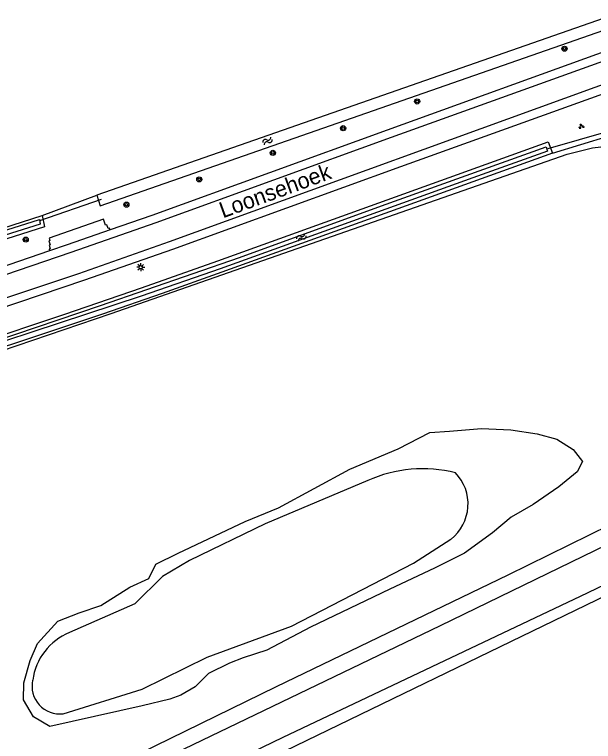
# Model space of a CAD drawing. Extents: x 134297 to 137000, y 403500 to 406000.
# Drawn here: x 136102.7 to 136193, y 404433.4 to 404546.7 of the extents above; entities that cross this region are included whole.
import ezdxf

# ---------------------------------------------------------------- set-up
doc = ezdxf.new("R2010")
doc.units = 0
for name, color, linetype in [('gg-afsc-draadraster', 7, 'Continuous'), ('gg-afsc-lijn draadraster', 7, 'Continuous'), ('gg-anno-openbare ruimte label', 7, 'Continuous'), ('gg-knt-verharding', 7, 'Continuous'), ('gg-knt-verharding nz', 7, 'Continuous'), ('gg-kntw-bovenkant insteek waterloop', 7, 'Continuous'), ('gg-kntw-waterlijn', 7, 'Continuous'), ('gg-kwrk-duiker nz buis', 7, 'Continuous'), ('gt-grn-groengrens', 7, 'Continuous'), ('gt-symb-boom', 7, 'Continuous'), ('gt-symb-groenvak', 7, 'Continuous'), ('gt-symb-lichtmast', 7, 'Continuous'), ('gt-symb-watersymbool', 7, 'Continuous')]:
    doc.layers.add(name, color=color, linetype=linetype)

# ---------------------------------------------------------------- blocks, each defined once
blk = doc.blocks.new('gt0-BOOM')
at = {"layer": 'gt-symb-boom'}
for radius in [0.4, 0.2]:
    blk.add_circle((0, 0), radius, dxfattribs=at)
blk = doc.blocks.new('gt0-GRVAK')
at = {"layer": 'gt-symb-groenvak'}
for p, q in [((-0.11, 0.19), (-0.23, 0.24)), ((-0.18, 0.15), (0.09, 0.15)), ((-0.09, 0.21), (-0.16, 0.32)), ((-0.05, 0.21), (-0.05, 0.39)), ((0, 0.21), (0.06, 0.32)), ((0.01, 0.19), (0.13, 0.24)), ((0.26, -0.05), (0.2, 0.06)), ((0.3, -0.05), (0.3, 0.13)), ((0.35, -0.05), (0.41, 0.06)), ((-0.24, -0.23), (-0.36, -0.18)), ((-0.32, -0.26), (-0.05, -0.26)), ((-0.23, -0.21), (-0.29, -0.09)), ((-0.18, -0.2), (-0.18, -0.02)), ((-0.14, -0.21), (-0.07, -0.09)), ((-0.12, -0.23), (0, -0.18)), ((0.24, -0.07), (0.12, -0.02)), ((0.17, -0.11), (0.44, -0.11)), ((0.37, -0.07), (0.49, -0.02))]:
    blk.add_line(p, q, dxfattribs=at)
blk = doc.blocks.new('gt0-WA')
at = {"layer": 'gt-symb-watersymbool'}
for centre, start, end in [((-0.32, 0.02), 28.0725, 151.9275), ((0.43, 0.42), 208.0725, 331.9275), ((-0.32, -0.43), 28.0725, 151.9275), ((0.43, -0.03), 208.0725, 331.9275)]:
    blk.add_arc(centre, 0.425, start, end, dxfattribs=at)
blk = doc.blocks.new('gt0-LMAST')
at = {"layer": 'gt-symb-lichtmast'}
for p, q in [((-0.18, 0.17), (-0.45, 0.44)), ((-0.01, 0.25), (-0.01, 0.62)), ((0.17, 0.17), (0.44, 0.44)), ((-0.26, 0), (-0.63, 0)), ((-0.18, -0.18), (-0.45, -0.45)), ((-0.01, -0.25), (-0.01, -0.63)), ((0.44, -0.45), (0.17, -0.18)), ((0.24, 0), (0.62, 0))]:
    blk.add_line(p, q, dxfattribs=at)
blk.add_circle((-0.01, 0), 0.25, dxfattribs=at)

msp = doc.modelspace()

# ---------------------------------------------------------------- linework, layer by layer
at = {"layer": 'gg-afsc-draadraster'}
msp.add_lwpolyline([(136027, 404470.76), (136054.87, 404479.77), (136100.69, 404494.3), (136117.79, 404500.1), (136188.91, 404524.97), (136192.84, 404525.94), (136197.24, 404526.47), (136206.06, 404526.86), (136212.49, 404527.78), (136214.08, 404527.22), (136216.9, 404521.12), (136220.14, 404513.53), (136226.74, 404497.62), (136232.4, 404483.42)], dxfattribs=at)
at = {"layer": 'gg-afsc-lijn draadraster'}
msp.add_lwpolyline([(136027, 404470.76), (136054.87, 404479.77), (136100.69, 404494.3), (136117.79, 404500.1), (136188.91, 404524.97), (136192.84, 404525.94), (136197.24, 404526.47), (136206.06, 404526.86), (136212.49, 404527.78), (136214.08, 404527.22), (136216.9, 404521.12), (136220.14, 404513.53), (136226.74, 404497.62), (136232.4, 404483.42)], dxfattribs=at)
at = {"layer": 'gg-knt-verharding'}
for points in [[(136197.46, 404542.1), (136195.9, 404541.36), (136160.84, 404528.67), (136124.12, 404515.41), (136117.65, 404513.15)], [(136197.49, 404535.45), (136195.13, 404534.58), (136162.9, 404522.97), (136127.36, 404510.1), (136113.62, 404505.3), (136099.76, 404500.63), (136086.34, 404496.28), (136076.86, 404493.32), (136066.07, 404490.19), (136055.56, 404487.24), (136045.09, 404484), (136034.7, 404480.64), (136023.56, 404476.68), (136011.23, 404471.9), (136004.74, 404469.15), (135995.87, 404465.09), (135985.92, 404460.27), (135976.35, 404455.35), (135965.54, 404449.33), (135957.74, 404444.76)], [(136117.65, 404513.15), (136117.52, 404513.43), (136117.33, 404513.38), (136117.11, 404513.92), (136116.93, 404513.87), (136116.63, 404514.8), (136108.16, 404511.88), (136108.26, 404511.51), (136108.09, 404511.43), (136108.28, 404510.84), (136108.11, 404510.78), (136108.3, 404510.2), (136108.11, 404510.14), (136108.2, 404509.87)], [(136117.65, 404513.15), (136110.96, 404510.8), (136108.2, 404509.87)], [(136108.2, 404509.87), (136098.64, 404506.63), (136084.48, 404502.05), (136070.65, 404497.79), (136060.14, 404494.87), (136049.92, 404491.85), (136039.52, 404488.61), (136028.95, 404485.07), (136018.55, 404481.26), (136009.16, 404477.58), (135999.86, 404473.65), (135990.66, 404469.37), (135981.82, 404465.02), (135975.54, 404461.77), (135967.96, 404457.68), (135960.58, 404453.48), (135954.61, 404449.98)]]:
    msp.add_lwpolyline(points, dxfattribs=at)
at = {"layer": 'gg-knt-verharding nz'}
for points in [[(136197.15, 404540.4), (136161.45, 404527.53), (136124.76, 404514.25), (136111.52, 404509.6), (136099.13, 404505.43), (136084.9, 404500.78), (136071.52, 404496.67), (136060.9, 404493.69), (136050.35, 404490.61), (136039.81, 404487.34), (136029.4, 404483.84), (136019.03, 404480.06), (136009.73, 404476.4), (136000.5, 404472.45), (135991.4, 404468.23), (135983.33, 404464.29), (135976.2, 404460.63), (135968.25, 404456.35), (135961.29, 404452.4), (135955.27, 404448.86)], [(136197.38, 404536.83), (136126.86, 404511.31), (136112.69, 404506.32), (136099.4, 404501.86), (136086.05, 404497.55), (136076.48, 404494.56), (136065.87, 404491.48), (136055.28, 404488.5), (136044.76, 404485.25), (136034.33, 404481.86), (136023.04, 404477.86), (136010.9, 404473.14), (136004.49, 404470.44), (135995.36, 404466.29), (135985.46, 404461.47), (135975.71, 404456.46), (135965.21, 404450.62), (135957.08, 404445.86)]]:
    msp.add_lwpolyline(points, dxfattribs=at)
at = {"layer": 'gg-kntw-bovenkant insteek waterloop'}
for p, q in [((136196.3, 404546.72), (136115.55, 404518.56)), ((136100.91, 404513.42), (136107.07, 404515.39))]:
    msp.add_line(p, q, dxfattribs=at)
for points in [[(136115.55, 404518.56), (136116.11, 404516.88), (136196.86, 404545.05)], [(136110.59, 404500), (136122.52, 404504.1), (136134.41, 404508.32), (136185.95, 404526.9), (136186.6, 404525.12)], [(136186.6, 404525.12), (136135.05, 404506.54), (136125.77, 404503.24), (136116.45, 404500)], [(136107.07, 404515.39), (136107.42, 404513.6), (136082.55, 404505.72), (136063.77, 404500)], [(136025.8, 404471.24), (136025.23, 404472.96), (136082.49, 404490.86), (136096.57, 404495.35), (136110.59, 404500)], [(136116.45, 404500), (136102.43, 404495.35), (136088.35, 404490.86), (136025.8, 404471.24)], [(136232.4, 404483.42), (136229.09, 404483.22), (136211.35, 404474.91), (136179.65, 404459.33), (136143.55, 404441.91), (136089.18, 404415.38), (136050.09, 404396.55), (136020.57, 404382.16), (135988.75, 404366.64), (135931.54, 404338.35), (135877.73, 404313.16)], [(136162.53, 404479.04), (136167.5, 404481.58), (136170.57, 404481.79), (136175.55, 404482.21), (136180.1, 404482), (136184.22, 404481.37), (136187.29, 404480.52), (136189.83, 404478.93), (136191.32, 404477.03), (136190.47, 404475.44), (136187.61, 404473.11), (136183.59, 404470.36), (136180.2, 404468.35), (136177.24, 404465.92), (136172.9, 404462.74), (136168.24, 404460.41), (136161.26, 404457.13), (136157.45, 404455.33), (136148.88, 404451.2), (136142.1, 404447.61), (136138.4, 404446.44), (136136.28, 404445.6), (136133, 404444.01), (136130.88, 404441.89), (136128.66, 404440.62), (136126.97, 404439.99), (136122.63, 404438.93), (136111.73, 404436.49), (136108.24, 404435.75), (136105.7, 404437.23), (136104.11, 404439.88), (136104.21, 404442.53), (136105.17, 404446.02), (136106.33, 404448.66), (136109.51, 404452.16), (136112.79, 404453.43), (136116.17, 404454.59), (136120.72, 404457.45), (136123.69, 404458.82), (136124.75, 404461.05), (136128.24, 404462.74), (136138.72, 404467.71), (136143.9, 404469.83), (136155.01, 404475.86), (136162.53, 404479.04)], [(136108.02, 404414.04), (136227.12, 404471.72), (136236.18, 404475.84)]]:
    msp.add_lwpolyline(points, dxfattribs=at)
at = {"layer": 'gg-kntw-waterlijn'}
for points in [[(136026.12, 404472.65), (136099.53, 404495.77), (136116.16, 404501.34), (136137.79, 404508.82), (136159.93, 404516.92), (136185.61, 404526.09), (136185.84, 404525.42), (136174.22, 404521.27), (136134.8, 404507.06), (136122.46, 404502.82), (136084.21, 404490.25), (136026.35, 404471.92), (136026.12, 404472.65)], [(136016.73, 404487.35), (136022.35, 404489.09), (136076.78, 404505.34), (136106.63, 404514.78), (136106.73, 404514.04), (136081.04, 404505.97), (136016.77, 404486.75)], [(135884.16, 404313.75), (135898.53, 404320.11), (135926.42, 404333.8), (135951.05, 404345.14), (135965.34, 404352.44), (136021.67, 404379.51), (136084.87, 404410.41), (136126.48, 404430.96), (136169.18, 404451.47), (136204.36, 404468.59), (136233.6, 404482.32), (136235.31, 404482.99), (136237.37, 404483.02), (136237.66, 404482.34)], [(135885.33, 404308.76), (135911.22, 404321.24), (135977.2, 404352.57), (135993.05, 404360.74), (136022.28, 404374.43), (136052.47, 404388.81), (136081.4, 404402.63), (136112.63, 404418.58), (136144.64, 404434.05), (136190.99, 404456.03), (136224.47, 404472.11), (136236.59, 404477.67), (136237.28, 404476.11)], [(136157.81, 404474.07), (136141.82, 404467.33), (136130.03, 404461.62), (136125.83, 404459.09), (136121.47, 404454.84), (136111.29, 404450.37)], [(136110.3, 404437.73), (136122.63, 404441.55), (136132.75, 404446.56), (136145.94, 404451.35), (136164.93, 404461.21), (136170.79, 404464.93)]]:
    msp.add_lwpolyline(points, dxfattribs=at)
for centre, radius, start, end in [((136166.36, 404455.28), 20.63, 75.5804, 114.4548), ((136166.44, 404470.42), 7.01, 308.4369, 43.8283), ((136114.85, 404441.7), 9.37, 112.2873, 172.3133), ((136109.8, 404442.03), 4.34, 167.8265, 276.5875)]:
    msp.add_arc(centre, radius, start, end, dxfattribs=at)
at = {"layer": 'gg-kwrk-duiker nz buis'}
for p, q in [((136195.64, 404528.57), (136185.91, 404525.77)), ((136106.68, 404514.61), (136116.31, 404517.92))]:
    msp.add_line(p, q, dxfattribs=at)
at = {"layer": 'gt-grn-groengrens'}
for p, q in [((136186.6, 404525.12), (136195.43, 404527.83)), ((136107.07, 404515.39), (136115.55, 404518.56))]:
    msp.add_line(p, q, dxfattribs=at)

# ---------------------------------------------------------------- block references
at = {"layer": 'gt-symb-boom'}
for p in [(136188.49, 404541.39), (136165.52, 404533.17), (136153.97, 404529), (136143.02, 404525.15), (136131.54, 404521.02), (136120.18, 404517.08), (136104.48, 404511.63)]:
    msp.add_blockref('gt0-BOOM', p, dxfattribs=at)
at = {"layer": 'gt-symb-groenvak'}
msp.add_blockref('gt0-GRVAK', (136191.11, 404529.28), dxfattribs=at)
at = {"layer": 'gt-symb-lichtmast'}
msp.add_blockref('gt0-LMAST', (136122.43, 404507.33), dxfattribs=at)
at = {"layer": 'gt-symb-watersymbool'}
for p, rotation in [((136142.23, 404527.03), -146.99293824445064), ((136147.52, 404512.01), -146.9929382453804)]:
    msp.add_blockref('gt0-WA', p, dxfattribs=dict(at, rotation=rotation))

# ---------------------------------------------------------------- texts
at = {"layer": 'gg-anno-openbare ruimte label'}
msp.add_text('Loonsehoek', height=2.5, rotation=20.1, dxfattribs=at).set_placement((136135.23, 404514.94))

doc.saveas('drawing.dxf')
